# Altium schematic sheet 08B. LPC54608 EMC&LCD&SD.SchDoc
size A3; CheckedBy: 赵金生; Author: 伍伟业; CompanyName: 广州周立功单片机科技有限公司; DocumentNumber: 9; SheetNumber: 8B; SheetTotal: 19; PageSetup: Record=PageOptions|CenterHorizontal=True|CenterVertical=True|PrintScale=1.00|XCorrection=1.00|YCorrection=1.00|PrintKind=0|BorderSize=5000000|LeftOffset=0|BottomOffset=0|Orientation=2|PaperLength=1000|PaperWidth=1000|Scale=100|PaperSource=7|PrintQuality=600|MediaType=1|DitherType=10|PaperKind=A4|PrintScaleMode=1; DesignDate: 2017-3-17; CheckDate: 2017-3-17; SheetName: LPC54608 EMC&LCD&SD; SheetVersion: V1.0; SheetDescription: LPC54608 EMC&LCD&SD
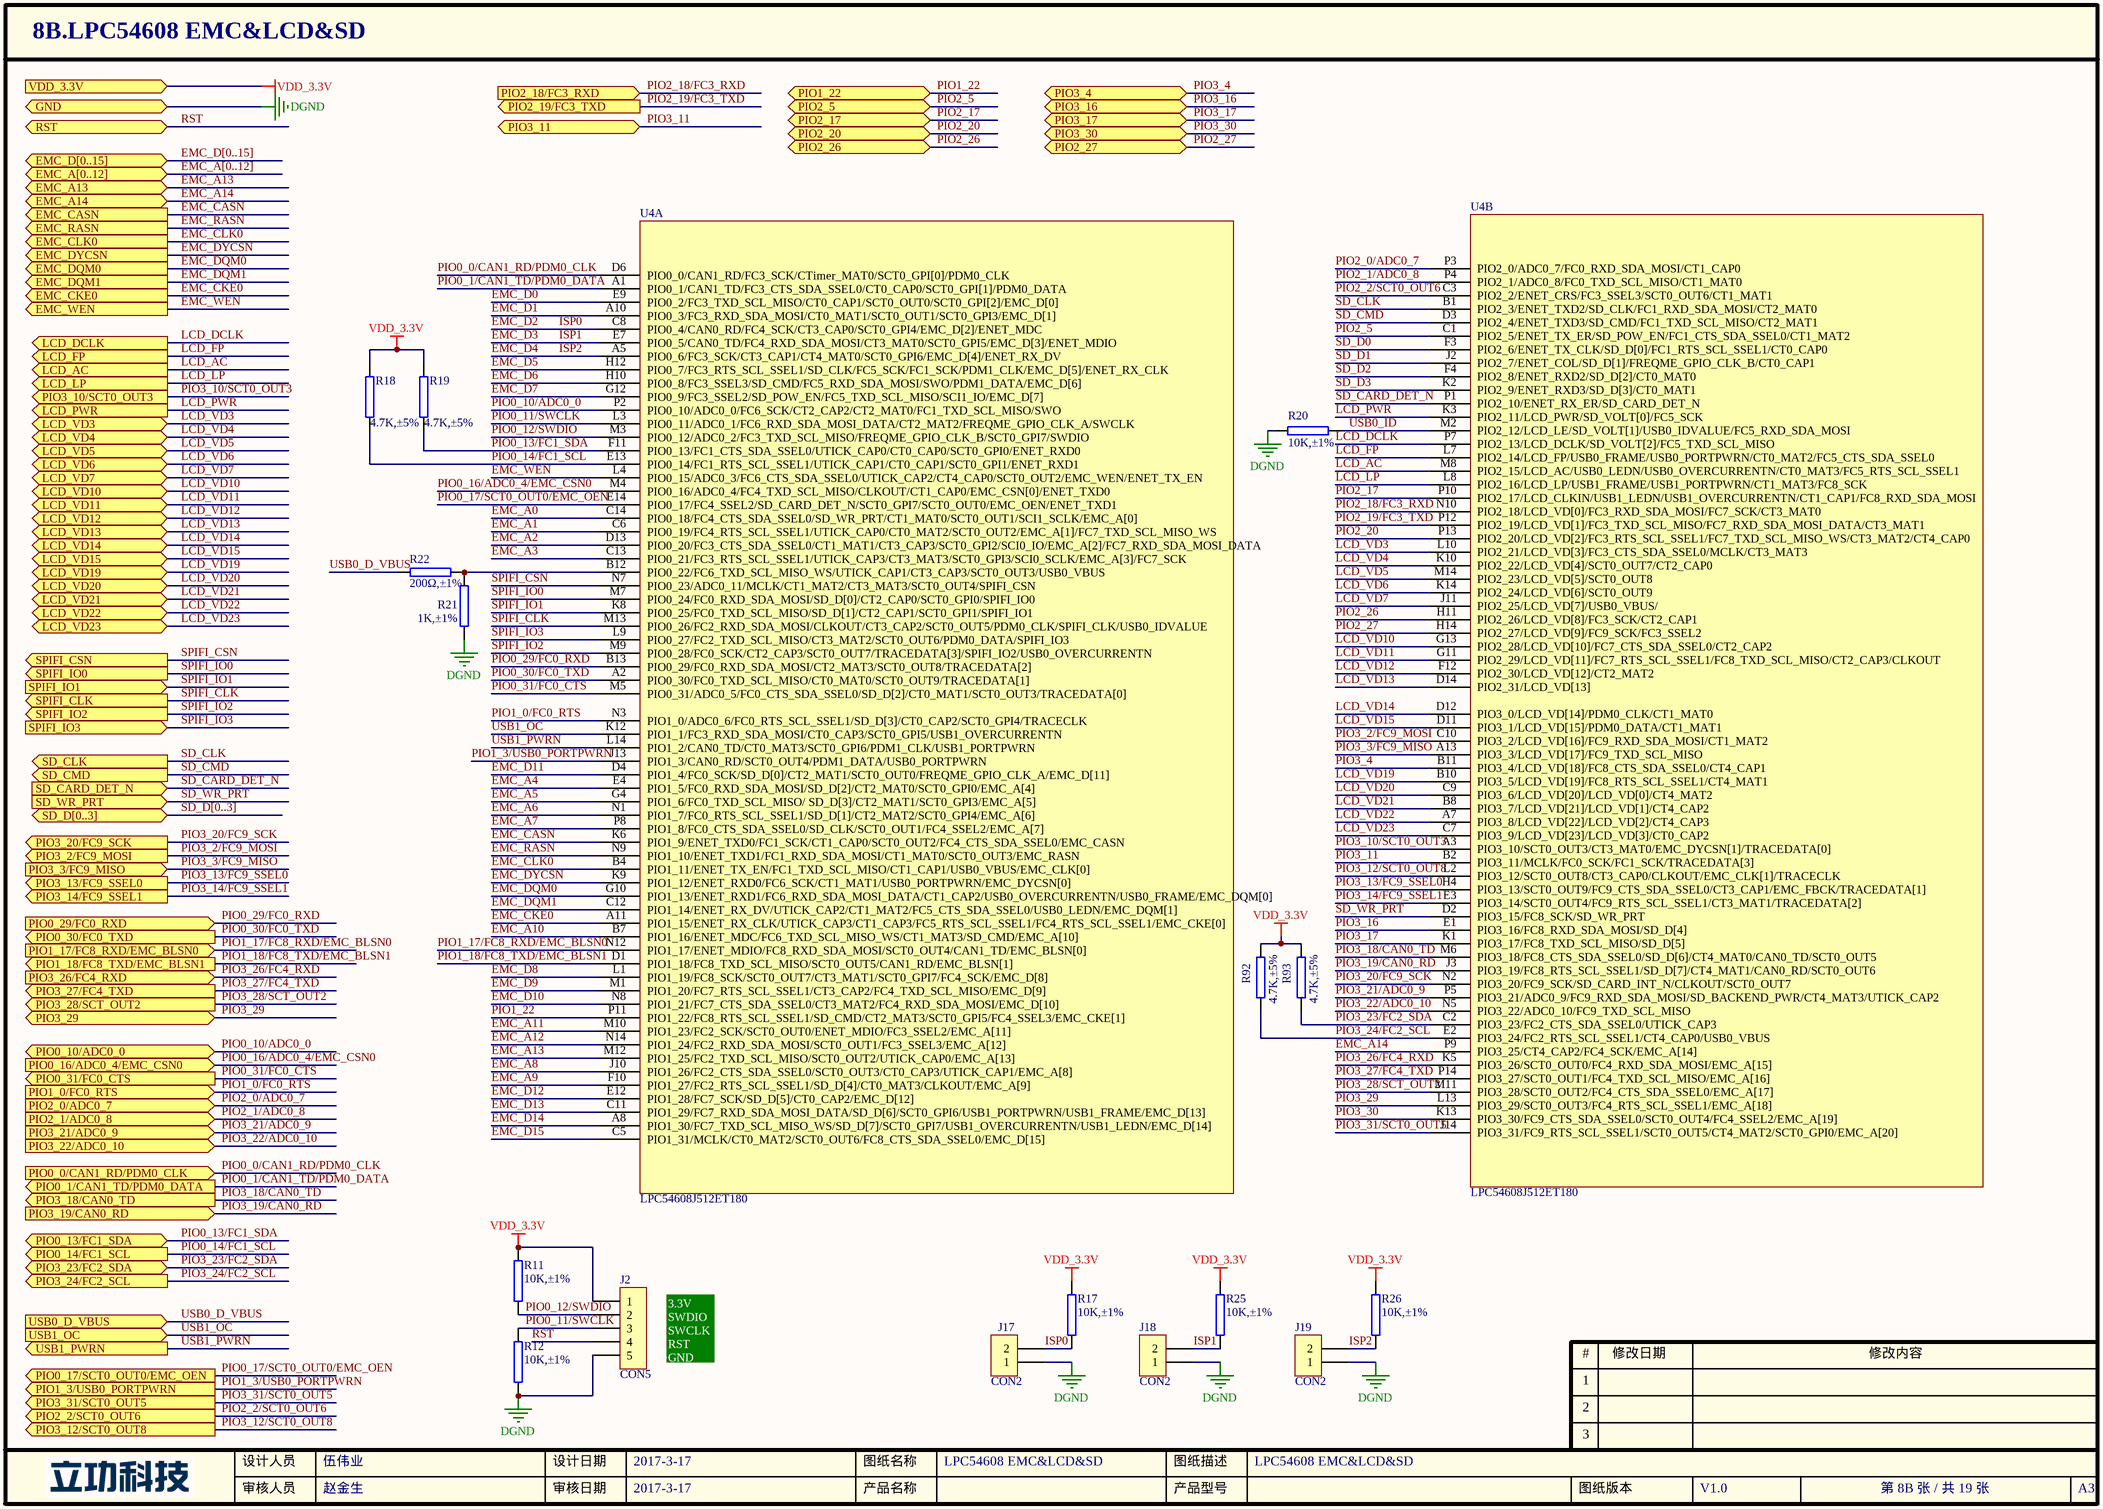
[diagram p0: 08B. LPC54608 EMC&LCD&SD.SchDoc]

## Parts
J2  CON5  [SIP-5-2.54-6.0-R90]
J17  CON2  [SIP-2-2.54]
J18  CON2  [SIP-2-2.54]
J19  CON2  [SIP-2-2.54]
R11  10K,±1%  [0402R]
R12  10K,±1%  [0402R]
R17  10K,±1%  [0402R]
R18  4.7K,±5%  [0402R]
R19  4.7K,±5%  [0402R]
R20  10K,±1%  [0402R]
R21  1K,±1%  [0402R]
R22  200Ω,±1%  [0402R]
R25  10K,±1%  [0402R]
R26  10K,±1%  [0402R]
R92  4.7K,±5%  [0402R]
R93  4.7K,±5%  [0402R]
U4  LPC54608J512ET180  [BGA180C80P14x14]  (parts A,B of 5)

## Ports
EMC_A13 (bidir), EMC_A14 (bidir), EMC_A[0..12] (bidir), EMC_CASN (out), EMC_CKE0 (out), EMC_CLK0 (out), EMC_D[0..15] (bidir), EMC_DQM0 (out), EMC_DQM1 (out), EMC_DYCSN (out), EMC_RASN (out), EMC_WEN (out), GND, LCD_AC (out), LCD_DCLK (out), LCD_FP (out), LCD_LP (out), LCD_PWR (out), LCD_VD3 (bidir), LCD_VD4 (bidir), LCD_VD5 (bidir), LCD_VD6 (bidir), LCD_VD7 (bidir), LCD_VD10 (bidir), LCD_VD11 (bidir), LCD_VD12 (bidir), LCD_VD13 (bidir), LCD_VD14 (bidir), LCD_VD15 (bidir), LCD_VD19 (bidir), LCD_VD20 (bidir), LCD_VD21 (bidir), LCD_VD22 (bidir), LCD_VD23 (bidir), PIO0_0/CAN1_RD/PDM0_CLK (in), PIO0_1/CAN1_TD/PDM0_DATA (out), PIO0_10/ADC0_0 (bidir), PIO0_13/FC1_SDA (bidir), PIO0_14/FC1_SCL (out), PIO0_16/ADC0_4/EMC_CSN0 (in), PIO0_17/SCT0_OUT0/EMC_OEN (out), PIO0_29/FC0_RXD (in), PIO0_30/FC0_TXD (out), PIO0_31/FC0_CTS (out), PIO1_0/FC0_RTS (in), PIO1_3/USB0_PORTPWRN (out), PIO1_17/FC8_RXD/EMC_BLSN0 (in), PIO1_18/FC8_TXD/EMC_BLSN1 (out), PIO1_22 (bidir), PIO2_0/ADC0_7 (in), PIO2_1/ADC0_8 (in), PIO2_2/SCT0_OUT6 (out), PIO2_5 (bidir), PIO2_17 (bidir), PIO2_18/FC3_RXD (in), PIO2_19/FC3_TXD (out), PIO2_20 (bidir), PIO2_26 (bidir), PIO2_27 (bidir), PIO3_2/FC9_MOSI (out), PIO3_3/FC9_MISO (in), PIO3_4 (bidir), PIO3_10/SCT0_OUT3 (out), PIO3_11 (bidir), PIO3_12/SCT0_OUT8 (out), PIO3_13/FC9_SSEL0 (out), PIO3_14/FC9_SSEL1 (out), PIO3_16 (bidir), PIO3_17 (bidir), PIO3_18/CAN0_TD (out), PIO3_19/CAN0_RD (in), PIO3_20/FC9_SCK (out), PIO3_21/ADC0_9 (in), PIO3_22/ADC0_10 (in), PIO3_23/FC2_SDA (bidir), PIO3_24/FC2_SCL (out), PIO3_26/FC4_RXD (in), PIO3_27/FC4_TXD (out), PIO3_28/SCT_OUT2 (out), PIO3_29 (bidir), PIO3_30 (bidir), PIO3_31/SCT0_OUT5 (out), RST (bidir), SD_CARD_DET_N (in), SD_CLK (out), SD_CMD (out), SD_D[0..3] (bidir), SD_WR_PRT (in), SPIFI_CLK (out), SPIFI_CSN (out), SPIFI_IO0 (out), SPIFI_IO1 (in), SPIFI_IO2 (out), SPIFI_IO3 (in), USB0_D_VBUS (in), USB1_OC (in), USB1_PWRN (out), VDD_3.3V (in)

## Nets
DGND: J2.5 J17.1 J18.1 J19.1 R12.1 R20.1 R21.1 ; port GND
VDD_3.3V: J2.1 R11.2 R17.2 R18.2 R19.2 R25.2 R26.2 R92.2 R93.2 ; port VDD_3.3V
EMC_A0: U4.C14(PIO0_18/FC4_CTS_SDA_SSEL0/SD_WR_PRT/CT1_MAT0/SCT0_OUT1/SCI1_SCLK/EMC_A[0])
EMC_A1: U4.C6(PIO0_19/FC4_RTS_SCL_SSEL1/UTICK_CAP0/CT0_MAT2/SCT0_OUT2/EMC_A[1]/FC7_TXD_SCL_MISO_WS)
EMC_A2: U4.D13(PIO0_20/FC3_CTS_SDA_SSEL0/CT1_MAT1/CT3_CAP3/SCT0_GPI2/SCI0_IO/EMC_A[2]/FC7_RXD_SDA_MOSI_DATA)
EMC_A3: U4.C13(PIO0_21/FC3_RTS_SCL_SSEL1/UTICK_CAP3/CT3_MAT3/SCT0_GPI3/SCI0_SCLK/EMC_A[3]/FC7_SCK)
EMC_A4: U4.E4(PIO1_5/FC0_RXD_SDA_MOSI/SD_D[2]/CT2_MAT0/SCT0_GPI0/EMC_A[4])
EMC_A5: U4.G4(PIO1_6/FC0_TXD_SCL_MISO/_SD_D[3]/CT2_MAT1/SCT0_GPI3/EMC_A[5])
EMC_A6: U4.N1(PIO1_7/FC0_RTS_SCL_SSEL1/SD_D[1]/CT2_MAT2/SCT0_GPI4/EMC_A[6])
EMC_A7: U4.P8(PIO1_8/FC0_CTS_SDA_SSEL0/SD_CLK/SCT0_OUT1/FC4_SSEL2/EMC_A[7])
EMC_A8: U4.J10(PIO1_26/FC2_CTS_SDA_SSEL0/SCT0_OUT3/CT0_CAP3/UTICK_CAP1/EMC_A[8])
EMC_A9: U4.F10(PIO1_27/FC2_RTS_SCL_SSEL1/SD_D[4]/CT0_MAT3/CLKOUT/EMC_A[9])
EMC_A10: U4.B7(PIO1_16/ENET_MDC/FC6_TXD_SCL_MISO_WS/CT1_MAT3/SD_CMD/EMC_A[10])
EMC_A11: U4.M10(PIO1_23/FC2_SCK/SCT0_OUT0/ENET_MDIO/FC3_SSEL2/EMC_A[11])
EMC_A12: U4.N14(PIO1_24/FC2_RXD_SDA_MOSI/SCT0_OUT1/FC3_SSEL3/EMC_A[12])
EMC_A13: U4.M12(PIO1_25/FC2_TXD_SCL_MISO/SCT0_OUT2/UTICK_CAP0/EMC_A[13]) ; port EMC_A13
EMC_A14: U4.P9(PIO3_25/CT4_CAP2/FC4_SCK/EMC_A[14]) ; port EMC_A14
EMC_CASN: U4.K6(PIO1_9/ENET_TXD0/FC1_SCK/CT1_CAP0/SCT0_OUT2/FC4_CTS_SDA_SSEL0/EMC_CASN) ; port EMC_CASN
EMC_CKE0: U4.A11(PIO1_15/ENET_RX_CLK/UTICK_CAP3/CT1_CAP3/FC5_RTS_SCL_SSEL1/FC4_RTS_SCL_SSEL1/EMC_CKE[0]) ; port EMC_CKE0
EMC_CLK0: U4.B4(PIO1_11/ENET_TX_EN/FC1_TXD_SCL_MISO/CT1_CAP1/USB0_VBUS/EMC_CLK[0]) ; port EMC_CLK0
EMC_D0: U4.E9(PIO0_2/FC3_TXD_SCL_MISO/CT0_CAP1/SCT0_OUT0/SCT0_GPI[2]/EMC_D[0])
EMC_D1: U4.A10(PIO0_3/FC3_RXD_SDA_MOSI/CT0_MAT1/SCT0_OUT1/SCT0_GPI3/EMC_D[1])
EMC_D2: J17.2 R17.1 U4.C8(PIO0_4/CAN0_RD/FC4_SCK/CT3_CAP0/SCT0_GPI4/EMC_D[2]/ENET_MDC)  [also labelled ISP0]
EMC_D3: J18.2 R25.1 U4.E7(PIO0_5/CAN0_TD/FC4_RXD_SDA_MOSI/CT3_MAT0/SCT0_GPI5/EMC_D[3]/ENET_MDIO)  [also labelled ISP1]
EMC_D4: J19.2 R26.1 U4.A5(PIO0_6/FC3_SCK/CT3_CAP1/CT4_MAT0/SCT0_GPI6/EMC_D[4]/ENET_RX_DV)  [also labelled ISP2]
EMC_D5: U4.H12(PIO0_7/FC3_RTS_SCL_SSEL1/SD_CLK/FC5_SCK/FC1_SCK/PDM1_CLK/EMC_D[5]/ENET_RX_CLK)
EMC_D6: U4.H10(PIO0_8/FC3_SSEL3/SD_CMD/FC5_RXD_SDA_MOSI/SWO/PDM1_DATA/EMC_D[6])
EMC_D7: U4.G12(PIO0_9/FC3_SSEL2/SD_POW_EN/FC5_TXD_SCL_MISO/SCI1_IO/EMC_D[7])
EMC_D8: U4.L1(PIO1_19/FC8_SCK/SCT0_OUT7/CT3_MAT1/SCT0_GPI7/FC4_SCK/EMC_D[8])
EMC_D9: U4.M1(PIO1_20/FC7_RTS_SCL_SSEL1/CT3_CAP2/FC4_TXD_SCL_MISO/EMC_D[9])
EMC_D10: U4.N8(PIO1_21/FC7_CTS_SDA_SSEL0/CT3_MAT2/FC4_RXD_SDA_MOSI/EMC_D[10])
EMC_D11: U4.D4(PIO1_4/FC0_SCK/SD_D[0]/CT2_MAT1/SCT0_OUT0/FREQME_GPIO_CLK_A/EMC_D[11])
EMC_D12: U4.E12(PIO1_28/FC7_SCK/SD_D[5]/CT0_CAP2/EMC_D[12])
EMC_D13: U4.C11(PIO1_29/FC7_RXD_SDA_MOSI_DATA/SD_D[6]/SCT0_GPI6/USB1_PORTPWRN/USB1_FRAME/EMC_D[13])
EMC_D14: U4.A8(PIO1_30/FC7_TXD_SCL_MISO_WS/SD_D[7]/SCT0_GPI7/USB1_OVERCURRENTN/USB1_LEDN/EMC_D[14])
EMC_D15: U4.C5(PIO1_31/MCLK/CT0_MAT2/SCT0_OUT6/FC8_CTS_SDA_SSEL0/EMC_D[15])
EMC_DQM0: U4.G10(PIO1_13/ENET_RXD1/FC6_RXD_SDA_MOSI_DATA/CT1_CAP2/USB0_OVERCURRENTN/USB0_FRAME/EMC_DQM[0]) ; port EMC_DQM0
EMC_DQM1: U4.C12(PIO1_14/ENET_RX_DV/UTICK_CAP2/CT1_MAT2/FC5_CTS_SDA_SSEL0/USB0_LEDN/EMC_DQM[1]) ; port EMC_DQM1
EMC_DYCSN: U4.K9(PIO1_12/ENET_RXD0/FC6_SCK/CT1_MAT1/USB0_PORTPWRN/EMC_DYCSN[0]) ; port EMC_DYCSN
EMC_RASN: U4.N9(PIO1_10/ENET_TXD1/FC1_RXD_SDA_MOSI/CT1_MAT0/SCT0_OUT3/EMC_RASN) ; port EMC_RASN
EMC_WEN: U4.L4(PIO0_15/ADC0_3/FC6_CTS_SDA_SSEL0/UTICK_CAP2/CT4_CAP0/SCT0_OUT2/EMC_WEN/ENET_TX_EN) ; port EMC_WEN
LCD_AC: U4.M8(PIO2_15/LCD_AC/USB0_LEDN/USB0_OVERCURRENTN/CT0_MAT3/FC5_RTS_SCL_SSEL1) ; port LCD_AC
LCD_DCLK: U4.P7(PIO2_13/LCD_DCLK/SD_VOLT[2]/FC5_TXD_SCL_MISO) ; port LCD_DCLK
LCD_FP: U4.L7(PIO2_14/LCD_FP/USB0_FRAME/USB0_PORTPWRN/CT0_MAT2/FC5_CTS_SDA_SSEL0) ; port LCD_FP
LCD_LP: U4.L8(PIO2_16/LCD_LP/USB1_FRAME/USB1_PORTPWRN/CT1_MAT3/FC8_SCK) ; port LCD_LP
LCD_PWR: U4.K3(PIO2_11/LCD_PWR/SD_VOLT[0]/FC5_SCK) ; port LCD_PWR
LCD_VD3: U4.L10(PIO2_21/LCD_VD[3]/FC3_CTS_SDA_SSEL0/MCLK/CT3_MAT3) ; port LCD_VD3
LCD_VD4: U4.K10(PIO2_22/LCD_VD[4]/SCT0_OUT7/CT2_CAP0) ; port LCD_VD4
LCD_VD5: U4.M14(PIO2_23/LCD_VD[5]/SCT0_OUT8) ; port LCD_VD5
LCD_VD6: U4.K14(PIO2_24/LCD_VD[6]/SCT0_OUT9) ; port LCD_VD6
LCD_VD7: U4.J11(PIO2_25/LCD_VD[7]/USB0_VBUS/) ; port LCD_VD7
LCD_VD10: U4.G13(PIO2_28/LCD_VD[10]/FC7_CTS_SDA_SSEL0/CT2_CAP2) ; port LCD_VD10
LCD_VD11: U4.G11(PIO2_29/LCD_VD[11]/FC7_RTS_SCL_SSEL1/FC8_TXD_SCL_MISO/CT2_CAP3/CLKOUT) ; port LCD_VD11
LCD_VD12: U4.F12(PIO2_30/LCD_VD[12]/CT2_MAT2) ; port LCD_VD12
LCD_VD13: U4.D14(PIO2_31/LCD_VD[13]) ; port LCD_VD13
LCD_VD14: U4.D12(PIO3_0/LCD_VD[14]/PDM0_CLK/CT1_MAT0) ; port LCD_VD14
LCD_VD15: U4.D11(PIO3_1/LCD_VD[15]/PDM0_DATA/CT1_MAT1) ; port LCD_VD15
LCD_VD19: U4.B10(PIO3_5/LCD_VD[19]/FC8_RTS_SCL_SSEL1/CT4_MAT1) ; port LCD_VD19
LCD_VD20: U4.C9(PIO3_6/LCD_VD[20]/LCD_VD[0]/CT4_MAT2) ; port LCD_VD20
LCD_VD21: U4.B8(PIO3_7/LCD_VD[21]/LCD_VD[1]/CT4_CAP2) ; port LCD_VD21
LCD_VD22: U4.A7(PIO3_8/LCD_VD[22]/LCD_VD[2]/CT4_CAP3) ; port LCD_VD22
LCD_VD23: U4.C7(PIO3_9/LCD_VD[23]/LCD_VD[3]/CT0_CAP2) ; port LCD_VD23
PIO0_0/CAN1_RD/PDM0_CLK: U4.D6(PIO0_0/CAN1_RD/FC3_SCK/CTimer_MAT0/SCT0_GPI[0]/PDM0_CLK) ; port PIO0_0/CAN1_RD/PDM0_CLK
PIO0_1/CAN1_TD/PDM0_DATA: U4.A1(PIO0_1/CAN1_TD/FC3_CTS_SDA_SSEL0/CT0_CAP0/SCT0_GPI[1]/PDM0_DATA) ; port PIO0_1/CAN1_TD/PDM0_DATA
PIO0_10/ADC0_0: U4.P2(PIO0_10/ADC0_0/FC6_SCK/CT2_CAP2/CT2_MAT0/FC1_TXD_SCL_MISO/SWO) ; port PIO0_10/ADC0_0
PIO0_11/SWCLK: J2.3 R12.2 U4.L3(PIO0_11/ADC0_1/FC6_RXD_SDA_MOSI_DATA/CT2_MAT2/FREQME_GPIO_CLK_A/SWCLK)
PIO0_12/SWDIO: J2.2 R11.1 U4.M3(PIO0_12/ADC0_2/FC3_TXD_SCL_MISO/FREQME_GPIO_CLK_B/SCT0_GPI7/SWDIO)
PIO0_13/FC1_SDA: R19.1 U4.F11(PIO0_13/FC1_CTS_SDA_SSEL0/UTICK_CAP0/CT0_CAP0/SCT0_GPI0/ENET_RXD0) ; port PIO0_13/FC1_SDA
PIO0_14/FC1_SCL: R18.1 U4.E13(PIO0_14/FC1_RTS_SCL_SSEL1/UTICK_CAP1/CT0_CAP1/SCT0_GPI1/ENET_RXD1) ; port PIO0_14/FC1_SCL
PIO0_16/ADC0_4/EMC_CSN0: U4.M4(PIO0_16/ADC0_4/FC4_TXD_SCL_MISO/CLKOUT/CT1_CAP0/EMC_CSN[0]/ENET_TXD0) ; port PIO0_16/ADC0_4/EMC_CSN0
PIO0_17/SCT0_OUT0/EMC_OEN: U4.E14(PIO0_17/FC4_SSEL2/SD_CARD_DET_N/SCT0_GPI7/SCT0_OUT0/EMC_OEN/ENET_TXD1) ; port PIO0_17/SCT0_OUT0/EMC_OEN
PIO0_29/FC0_RXD: U4.B13(PIO0_29/FC0_RXD_SDA_MOSI/CT2_MAT3/SCT0_OUT8/TRACEDATA[2]) ; port PIO0_29/FC0_RXD
PIO0_30/FC0_TXD: U4.A2(PIO0_30/FC0_TXD_SCL_MISO/CT0_MAT0/SCT0_OUT9/TRACEDATA[1]) ; port PIO0_30/FC0_TXD
PIO0_31/FC0_CTS: U4.M5(PIO0_31/ADC0_5/FC0_CTS_SDA_SSEL0/SD_D[2]/CT0_MAT1/SCT0_OUT3/TRACEDATA[0]) ; port PIO0_31/FC0_CTS
PIO1_0/FC0_RTS: U4.N3(PIO1_0/ADC0_6/FC0_RTS_SCL_SSEL1/SD_D[3]/CT0_CAP2/SCT0_GPI4/TRACECLK) ; port PIO1_0/FC0_RTS
PIO1_3/USB0_PORTPWRN: U4.J13(PIO1_3/CAN0_RD/SCT0_OUT4/PDM1_DATA/USB0_PORTPWRN) ; port PIO1_3/USB0_PORTPWRN
PIO1_17/FC8_RXD/EMC_BLSN0: U4.N12(PIO1_17/ENET_MDIO/FC8_RXD_SDA_MOSI/SCT0_OUT4/CAN1_TD/EMC_BLSN[0]) ; port PIO1_17/FC8_RXD/EMC_BLSN0
PIO1_18/FC8_TXD/EMC_BLSN1: U4.D1(PIO1_18/FC8_TXD_SCL_MISO/SCT0_OUT5/CAN1_RD/EMC_BLSN[1]) ; port PIO1_18/FC8_TXD/EMC_BLSN1
PIO1_22: U4.P11(PIO1_22/FC8_RTS_SCL_SSEL1/SD_CMD/CT2_MAT3/SCT0_GPI5/FC4_SSEL3/EMC_CKE[1]) ; port PIO1_22
PIO2_0/ADC0_7: U4.P3(PIO2_0/ADC0_7/FC0_RXD_SDA_MOSI/CT1_CAP0) ; port PIO2_0/ADC0_7
PIO2_1/ADC0_8: U4.P4(PIO2_1/ADC0_8/FC0_TXD_SCL_MISO/CT1_MAT0) ; port PIO2_1/ADC0_8
PIO2_2/SCT0_OUT6: U4.C3(PIO2_2/ENET_CRS/FC3_SSEL3/SCT0_OUT6/CT1_MAT1) ; port PIO2_2/SCT0_OUT6
PIO2_5: U4.C1(PIO2_5/ENET_TX_ER/SD_POW_EN/FC1_CTS_SDA_SSEL0/CT1_MAT2) ; port PIO2_5
PIO2_17: U4.P10(PIO2_17/LCD_CLKIN/USB1_LEDN/USB1_OVERCURRENTN/CT1_CAP1/FC8_RXD_SDA_MOSI) ; port PIO2_17
PIO2_18/FC3_RXD: U4.N10(PIO2_18/LCD_VD[0]/FC3_RXD_SDA_MOSI/FC7_SCK/CT3_MAT0) ; port PIO2_18/FC3_RXD
PIO2_19/FC3_TXD: U4.P12(PIO2_19/LCD_VD[1]/FC3_TXD_SCL_MISO/FC7_RXD_SDA_MOSI_DATA/CT3_MAT1) ; port PIO2_19/FC3_TXD
PIO2_20: U4.P13(PIO2_20/LCD_VD[2]/FC3_RTS_SCL_SSEL1/FC7_TXD_SCL_MISO_WS/CT3_MAT2/CT4_CAP0) ; port PIO2_20
PIO2_26: U4.H11(PIO2_26/LCD_VD[8]/FC3_SCK/CT2_CAP1) ; port PIO2_26
PIO2_27: U4.H14(PIO2_27/LCD_VD[9]/FC9_SCK/FC3_SSEL2) ; port PIO2_27
PIO3_2/FC9_MOSI: U4.C10(PIO3_2/LCD_VD[16]/FC9_RXD_SDA_MOSI/CT1_MAT2) ; port PIO3_2/FC9_MOSI
PIO3_3/FC9_MISO: U4.A13(PIO3_3/LCD_VD[17]/FC9_TXD_SCL_MISO) ; port PIO3_3/FC9_MISO
PIO3_4: U4.B11(PIO3_4/LCD_VD[18]/FC8_CTS_SDA_SSEL0/CT4_CAP1) ; port PIO3_4
PIO3_10/SCT0_OUT3: U4.A3(PIO3_10/SCT0_OUT3/CT3_MAT0/EMC_DYCSN[1]/TRACEDATA[0]) ; port PIO3_10/SCT0_OUT3
PIO3_11: U4.B2(PIO3_11/MCLK/FC0_SCK/FC1_SCK/TRACEDATA[3]) ; port PIO3_11
PIO3_12/SCT0_OUT8: U4.L2(PIO3_12/SCT0_OUT8/CT3_CAP0/CLKOUT/EMC_CLK[1]/TRACECLK) ; port PIO3_12/SCT0_OUT8
PIO3_13/FC9_SSEL0: U4.H4(PIO3_13/SCT0_OUT9/FC9_CTS_SDA_SSEL0/CT3_CAP1/EMC_FBCK/TRACEDATA[1]) ; port PIO3_13/FC9_SSEL0
PIO3_14/FC9_SSEL1: U4.E3(PIO3_14/SCT0_OUT4/FC9_RTS_SCL_SSEL1/CT3_MAT1/TRACEDATA[2]) ; port PIO3_14/FC9_SSEL1
PIO3_16: U4.E1(PIO3_16/FC8_RXD_SDA_MOSI/SD_D[4]) ; port PIO3_16
PIO3_17: U4.K1(PIO3_17/FC8_TXD_SCL_MISO/SD_D[5]) ; port PIO3_17
PIO3_18/CAN0_TD: U4.M6(PIO3_18/FC8_CTS_SDA_SSEL0/SD_D[6]/CT4_MAT0/CAN0_TD/SCT0_OUT5) ; port PIO3_18/CAN0_TD
PIO3_19/CAN0_RD: U4.J3(PIO3_19/FC8_RTS_SCL_SSEL1/SD_D[7]/CT4_MAT1/CAN0_RD/SCT0_OUT6) ; port PIO3_19/CAN0_RD
PIO3_20/FC9_SCK: U4.N2(PIO3_20/FC9_SCK/SD_CARD_INT_N/CLKOUT/SCT0_OUT7) ; port PIO3_20/FC9_SCK
PIO3_21/ADC0_9: U4.P5(PIO3_21/ADC0_9/FC9_RXD_SDA_MOSI/SD_BACKEND_PWR/CT4_MAT3/UTICK_CAP2) ; port PIO3_21/ADC0_9
PIO3_22/ADC0_10: U4.N5(PIO3_22/ADC0_10/FC9_TXD_SCL_MISO) ; port PIO3_22/ADC0_10
PIO3_23/FC2_SDA: R93.1 U4.C2(PIO3_23/FC2_CTS_SDA_SSEL0/UTICK_CAP3) ; port PIO3_23/FC2_SDA
PIO3_24/FC2_SCL: R92.1 U4.E2(PIO3_24/FC2_RTS_SCL_SSEL1/CT4_CAP0/USB0_VBUS) ; port PIO3_24/FC2_SCL
PIO3_26/FC4_RXD: U4.K5(PIO3_26/SCT0_OUT0/FC4_RXD_SDA_MOSI/EMC_A[15]) ; port PIO3_26/FC4_RXD
PIO3_27/FC4_TXD: U4.P14(PIO3_27/SCT0_OUT1/FC4_TXD_SCL_MISO/EMC_A[16]) ; port PIO3_27/FC4_TXD
PIO3_28/SCT_OUT2: U4.M11(PIO3_28/SCT0_OUT2/FC4_CTS_SDA_SSEL0/EMC_A[17]) ; port PIO3_28/SCT_OUT2
PIO3_29: U4.L13(PIO3_29/SCT0_OUT3/FC4_RTS_SCL_SSEL1/EMC_A[18]) ; port PIO3_29
PIO3_30: U4.K13(PIO3_30/FC9_CTS_SDA_SSEL0/SCT0_OUT4/FC4_SSEL2/EMC_A[19]) ; port PIO3_30
PIO3_31/SCT0_OUT5: U4.J14(PIO3_31/FC9_RTS_SCL_SSEL1/SCT0_OUT5/CT4_MAT2/SCT0_GPI0/EMC_A[20]) ; port PIO3_31/SCT0_OUT5
RST: J2.4 ; port RST
SD_CARD_DET_N: U4.P1(PIO2_10/ENET_RX_ER/SD_CARD_DET_N) ; port SD_CARD_DET_N
SD_CLK: U4.B1(PIO2_3/ENET_TXD2/SD_CLK/FC1_RXD_SDA_MOSI/CT2_MAT0) ; port SD_CLK
SD_CMD: U4.D3(PIO2_4/ENET_TXD3/SD_CMD/FC1_TXD_SCL_MISO/CT2_MAT1) ; port SD_CMD
SD_D0: U4.F3(PIO2_6/ENET_TX_CLK/SD_D[0]/FC1_RTS_SCL_SSEL1/CT0_CAP0)
SD_D1: U4.J2(PIO2_7/ENET_COL/SD_D[1]/FREQME_GPIO_CLK_B/CT0_CAP1)
SD_D2: U4.F4(PIO2_8/ENET_RXD2/SD_D[2]/CT0_MAT0)
SD_D3: U4.K2(PIO2_9/ENET_RXD3/SD_D[3]/CT0_MAT1)
SD_WR_PRT: U4.D2(PIO3_15/FC8_SCK/SD_WR_PRT) ; port SD_WR_PRT
SPIFI_CLK: U4.M13(PIO0_26/FC2_RXD_SDA_MOSI/CLKOUT/CT3_CAP2/SCT0_OUT5/PDM0_CLK/SPIFI_CLK/USB0_IDVALUE) ; port SPIFI_CLK
SPIFI_CSN: U4.N7(PIO0_23/ADC0_11/MCLK/CT1_MAT2/CT3_MAT3/SCT0_OUT4/SPIFI_CSN) ; port SPIFI_CSN
SPIFI_IO0: U4.M7(PIO0_24/FC0_RXD_SDA_MOSI/SD_D[0]/CT2_CAP0/SCT0_GPI0/SPIFI_IO0) ; port SPIFI_IO0
SPIFI_IO1: U4.K8(PIO0_25/FC0_TXD_SCL_MISO/SD_D[1]/CT2_CAP1/SCT0_GPI1/SPIFI_IO1) ; port SPIFI_IO1
SPIFI_IO2: U4.M9(PIO0_28/FC0_SCK/CT2_CAP3/SCT0_OUT7/TRACEDATA[3]/SPIFI_IO2/USB0_OVERCURRENTN) ; port SPIFI_IO2
SPIFI_IO3: U4.L9(PIO0_27/FC2_TXD_SCL_MISO/CT3_MAT2/SCT0_OUT6/PDM0_DATA/SPIFI_IO3) ; port SPIFI_IO3
USB0_D_VBUS: R22.2 ; port USB0_D_VBUS
USB0_ID: R20.2 U4.M2(PIO2_12/LCD_LE/SD_VOLT[1]/USB0_IDVALUE/FC5_RXD_SDA_MOSI)
USB1_OC: U4.K12(PIO1_1/FC3_RXD_SDA_MOSI/CT0_CAP3/SCT0_GPI5/USB1_OVERCURRENTN) ; port USB1_OC
USB1_PWRN: U4.L14(PIO1_2/CAN0_TD/CT0_MAT3/SCT0_GPI6/PDM1_CLK/USB1_PORTPWRN) ; port USB1_PWRN
NetR21_2: R21.2 R22.1 U4.B12(PIO0_22/FC6_TXD_SCL_MISO_WS/UTICK_CAP1/CT3_CAP3/SCT0_OUT3/USB0_VBUS)

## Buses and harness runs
bus EMC_A[0..12] = port EMC_A[0..12]
bus EMC_D[0..15] = port EMC_D[0..15]
bus SD_D[0..3] = port SD_D[0..3]

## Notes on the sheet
- (near J2) 3.3V
  SWDIO
  SWCLK
  RST
  GND

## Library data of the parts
J2 = CON5: Connector
J17-J19 = CON2: Connector
R11 R12 R17 R20 R25 R26 = 1.01.17.0034: 10K,±1%,0402,RALEC,RoHS; 名称: 电阻; 封装: 0402; 设备封装名称: R0402_10K_1%; 贴片和直插: SMT; 器件优选方案: 正常状态，可以选用
R18 R19 R92 R93 = 1.01.17.0019: 4.7K,±5%,0402,RALEC,RoHS; 名称: 电阻; 封装: 0402; 设备封装名称: R0402_4.7K; 贴片和直插: SMT; 器件优选方案: 正常状态，可以选用
R21 = 1.01.17.0016: 1K,±1%,0402,RALEC,RoHS; 名称: 电阻; 封装: 0402; 设备封装名称: R0402_1K_1%; 贴片和直插: SMT; 器件优选方案: 正常状态，可以选用
R22 = 1.01.17.0073: 200Ω,±1%,0402,RoHS; 名称: 电阻; 封装: 0402; 设备封装名称: R0402_200R_1%; 厂商: Ralec; 贴片和直插: SMT; 器件优选方案: 正常状态，可以选用
U4 = 1.05.02.0192: LPC54608J512ET180,TFBGA180,NXP,RoHS; 名称: 集成电路(临时); 贴片和直插: SMT; PCB备注: 170314lmd; 器件优选方案: 临时/偏门物料/不主推物料，谨慎选用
